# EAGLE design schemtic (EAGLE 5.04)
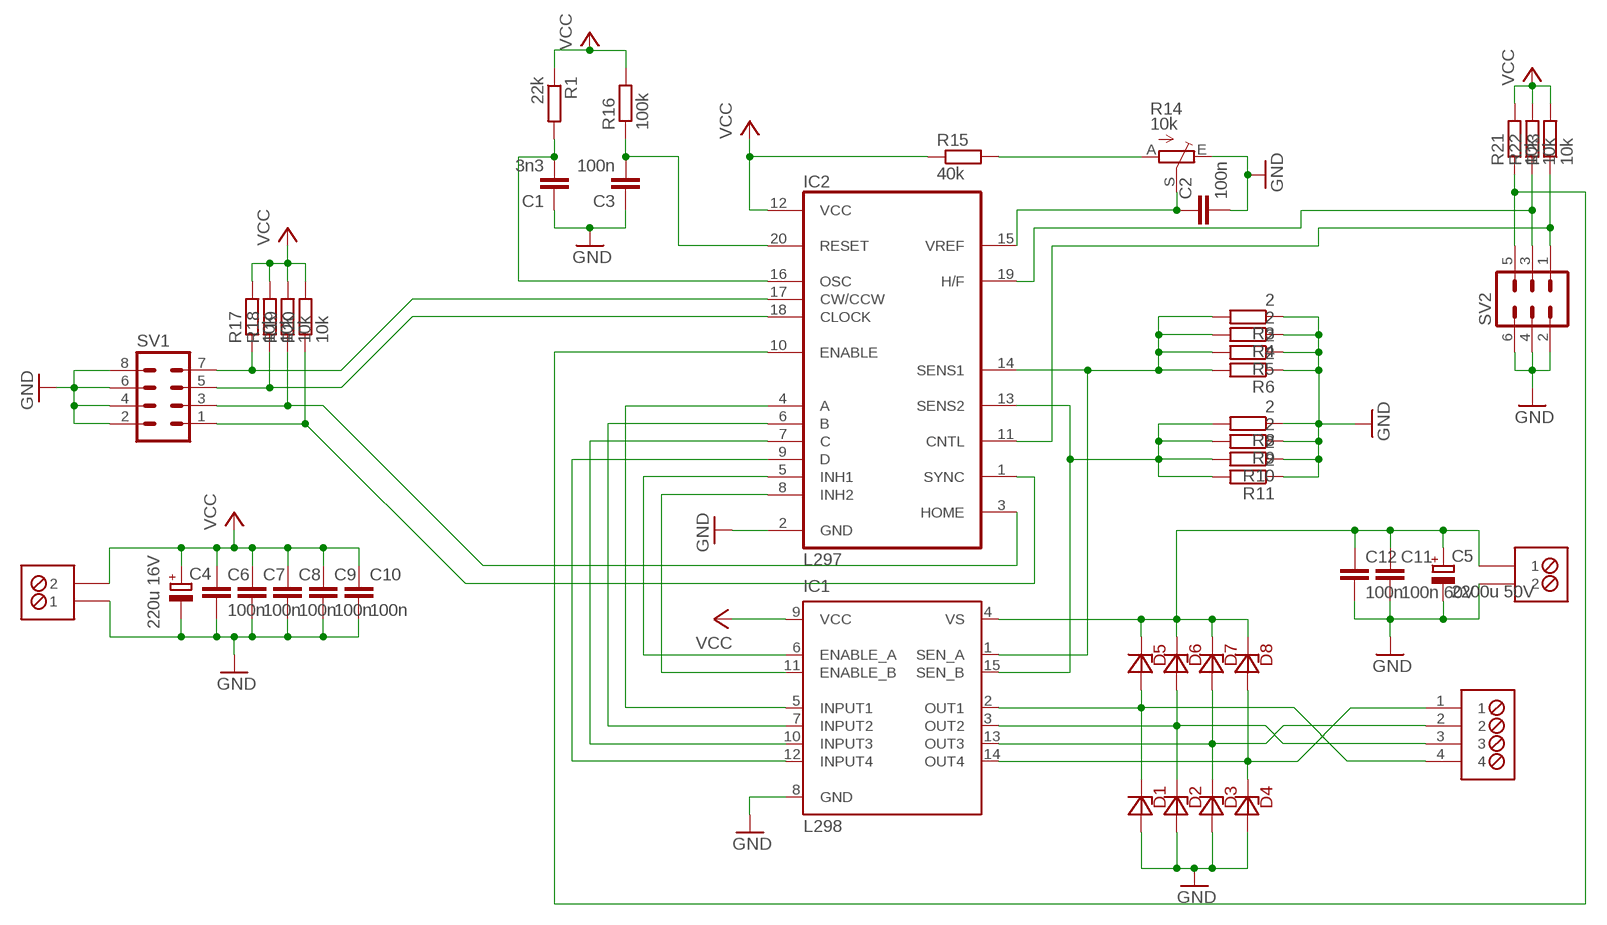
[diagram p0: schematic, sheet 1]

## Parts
C1  3n3  C-EU050-030X075  [C050-030X075]
C2  100n  C-EUC0603  [C0603]
C3  100n  C-EUC0805  [C0805]
C4  220u 16V  CPOL-EUE5-13  [E5-13]
C5  2200u 50V  CPOL-EUE7.5-16  [E7,5-16]
C6  100n  C-EUC0603  [C0603]
C7  100n  C-EUC0603  [C0603]
C8  100n  C-EUC0603  [C0603]
C9  100n  C-EUC0603  [C0603]
C10  100n  C-EUC0603  [C0603]
C11  100n 60V  C-EU050-055X075  [C050-055X075]
C12  100n  C-EU050-055X075  [C050-055X075]
CON1  LISTAWA_ZACISKOWA5MM_4X1  [LISTAWA_ZACISKOWA5MM_4X1]
CON2  LISTWA_ZACISKOWA5MM_2X1  [LISTWA_ZACISKOWA5MM_2X1]
CON3  LISTWA_ZACISKOWA5MM_2X1  [LISTWA_ZACISKOWA5MM_2X1]
D1  1N5822  [DO-27]
D2  1N5822  [DO-27]
D3  1N5822  [DO-27]
D4  1N5822  [DO-27]
D5  1N5822  [DO-27]
D6  1N5822  [DO-27]
D7  1N5822  [DO-27]
D8  1N5822  [DO-27]
IC1  L298  [MULTIWATT-15]
IC2  L297  [DIL20]
R1  22k  R-EU_0207/7  [0207/7]
R3  2  R-EU_0411/15  [0411/15]
R4  2  R-EU_0411/15  [0411/15]
R5  2  R-EU_0411/15  [0411/15]
R6  2  R-EU_0411/15  [0411/15]
R8  2  R-EU_0411/15  [0411/15]
R9  2  R-EU_0411/15  [0411/15]
R10  2  R-EU_0411/15  [0411/15]
R11  2  R-EU_0411/15  [0411/15]
R14  10k  TRIM_EU-S63X  [S63X]
R15  40k  R-EU_0207/7  [0207/7]
R16  100k  R-EU_0207/7  [0207/7]
R17  10k  R-EU_R0603  [R0603]
R18  10k  R-EU_R0603  [R0603]
R19  10k  R-EU_R0603  [R0603]
R20  10k  R-EU_R0603  [R0603]
R21  10k  R-EU_R0603  [R0603]
R22  10k  R-EU_R0603  [R0603]
R23  10k  R-EU_R0603  [R0603]
SV1  MA04-2  [MA04-2]
SV2  MA03-2  [MA03-2]

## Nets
GND: C1.1 C2.2 C3.1 C4.- C5.- C6.2 C7.2 C8.2 C9.2 C10.2 C11.2 C12.2 CON2.P$2 CON3.P$1 D1.CAT D2.CAT D3.CAT D4.CAT IC1.8(GND) IC2.2(GND) R3.1 R4.1 R5.1 R6.1 R8.1 R9.1 R10.1 R11.1 R14.E SV1.2 SV1.4 SV1.6 SV1.8 SV2.2 SV2.4 SV2.6
N$1: IC1.5(INPUT1) IC2.4(A)
N$2: IC1.7(INPUT2) IC2.6(B)
N$3: IC1.10(INPUT3) IC2.7(C)
N$4: IC1.12(INPUT4) IC2.9(D)
N$5: IC1.6(ENABLE_A) IC2.5(INH1)
N$6: IC1.11(ENABLE_B) IC2.8(INH2)
N$7: IC1.1(SEN_A) IC2.14(SENS1) R3.2 R4.2 R5.2 R6.2
N$8: IC1.15(SEN_B) IC2.13(SENS2) R8.2 R9.2 R10.2 R11.2
N$9: C1.2 IC2.16(OSC) R1.2
N$10: CON1.4 D1.AN D5.CAT IC1.2(OUT1)
N$11: IC2.18(CLOCK) R18.1 SV1.5
N$12: IC2.17(CW/CCW) R17.1 SV1.7
N$13: CON1.1 D4.AN D8.CAT IC1.14(OUT4)
N$14: C2.1 IC2.15(VREF) R14.S
N$15: C5.+ C11.1 C12.1 CON2.P$1 D5.AN D6.AN D7.AN D8.AN IC1.4(VS)
N$16: R14.A R15.2
N$17: IC2.19(H/F) R22.1 SV2.3
N$18: IC2.11(CNTL) R23.1 SV2.1
N$19: C3.2 IC2.20(RESET) R16.1
N$20: CON1.2 D3.AN D7.CAT IC1.13(OUT3)
N$22: IC2.10(ENABLE) R21.1 SV2.5
N$25: IC2.3(HOME) R19.1 SV1.3
N$26: IC2.1(SYNC) R20.1 SV1.1
N$27: CON1.3 D2.AN D6.CAT IC1.3(OUT2)
VCC: C4.+ C6.1 C7.1 C8.1 C9.1 C10.1 CON3.P$2 IC1.9(VCC) IC2.12(VCC) R1.1 R15.1 R16.2 R17.2 R18.2 R19.2 R20.2 R21.2 R22.2 R23.2

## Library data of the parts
C1-C3 C6-C12 = rcl:C-EU: CAPACITOR, European symbol
C4 C5 = rcl:CPOL-EU: POLARIZED CAPACITOR, European symbol
CON1 = konektory:LISTAWA_ZACISKOWA5MM_4X1
CON2 CON3 = konektory:LISTWA_ZACISKOWA5MM_2X1
D1-D8 = diody:1N5822: SCHOTTKY RECTIFIER 3A 40V
IC1 = st-microelectronics:L298: DUAL FULL-BRIDGE DRIVER
IC2 = st-microelectronics:L297: STEPPER MOTOR CONTROLLER
R1 R3-R6 R8-R11 R15-R23 = rcl:R-EU_: RESISTOR, European symbol
R14 = pot:TRIM_EU-: POTENTIOMETER
SV1 = con-lstb:MA04-2: PIN HEADER
SV2 = con-lstb:MA03-2: PIN HEADER

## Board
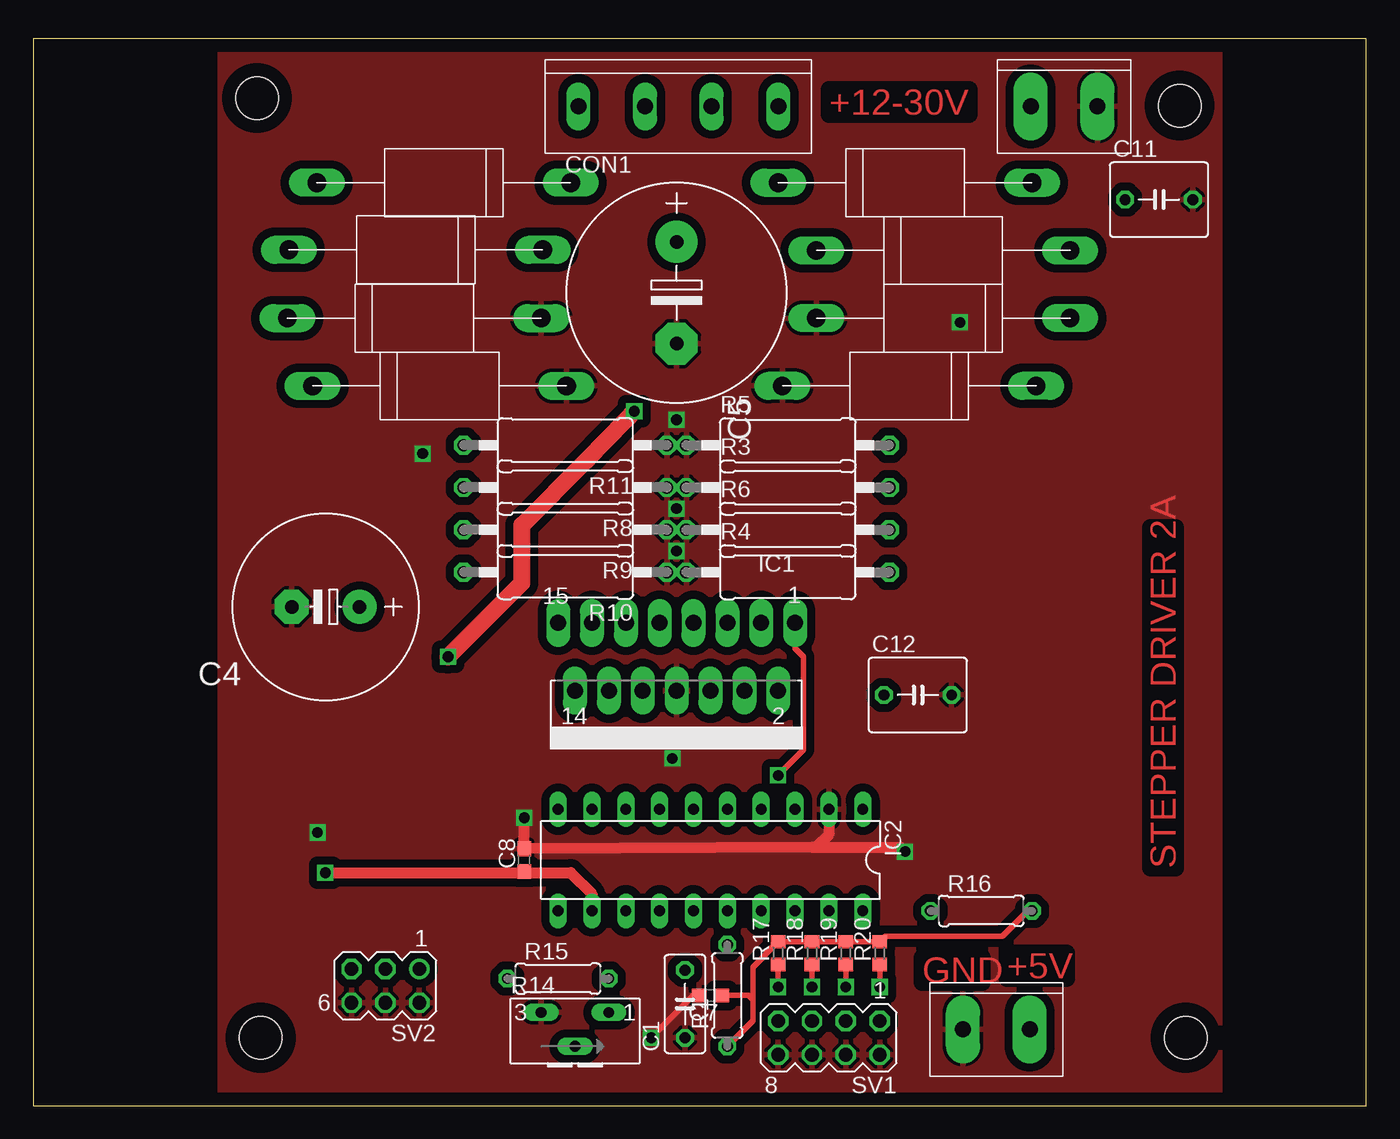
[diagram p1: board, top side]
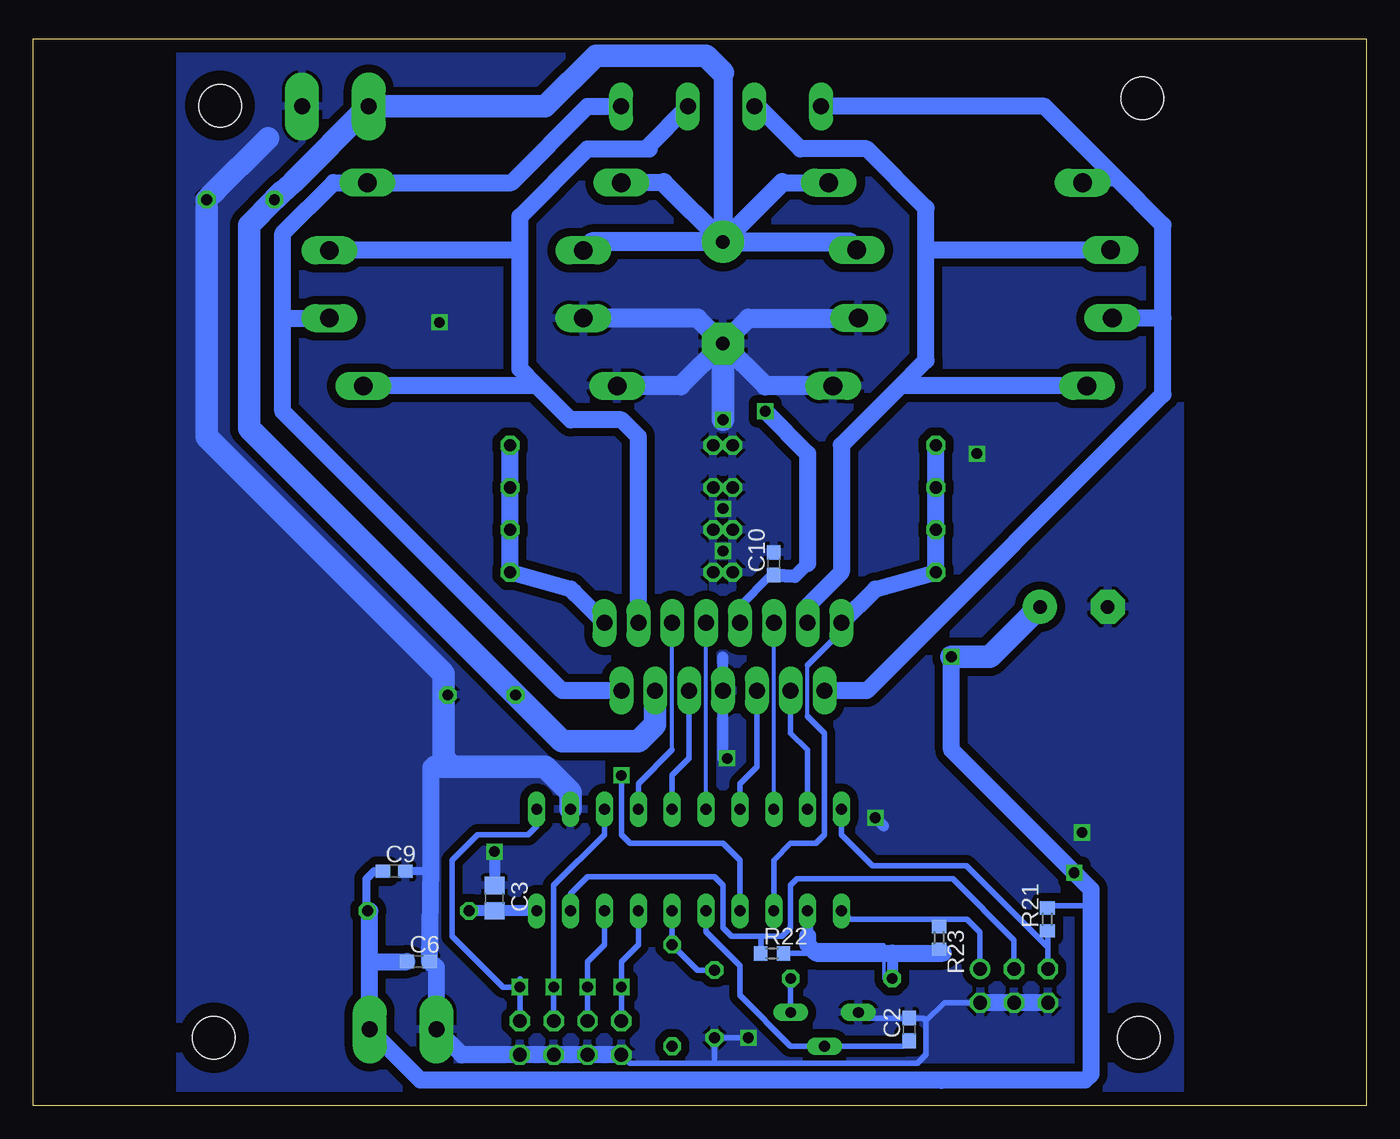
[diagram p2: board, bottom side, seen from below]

Size 100 x 80 mm. Coordinates in mm from the lower left corner, seen from the top.
Outline: 0,0 100,0 100,80 0,80 0,0
Copper layers (1*16): Top 0.035mm / dielectric 1.5mm / Bottom 0.035mm
Design rules "default": minimum track width 10mil, minimum drill 24mil, track to track 8mil, track to pad 8mil, pad to pad 8mil, via to via 8mil, smd to smd 8mil, copper to edge 40mil, drill to drill 8mil, minimum pad ring 10mil, minimum via ring 8mil, stop-mask expansion 4mil, vias tented up to drill 0mil, thermal gap 10mil
Holes 3.2 mm at 17.05,5.08 86.45,5.08 16.78,75.56 86,75

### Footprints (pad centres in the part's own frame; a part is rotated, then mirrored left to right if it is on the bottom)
C050-030X075 = drill 0.813 octagon: 1 -2.54,0; 2 2.54,0
C0603 = smd 1.1 x 1: 1 -0.85,0; 2 0.85,0
C0805 = smd 1.3 x 1.5: 1 -0.95,0; 2 0.95,0
E5-13 = drill 1.016 pad 2.54 round: + -2.54,0 | drill 1.016 pad 2.54 octagon: - 2.54,0
E7,5-16 = drill 1.016 pad 3.15 round: + -3.81,0 | drill 1.016 pad 3.15 octagon: - 3.81,0
C050-055X075 = drill 0.813 octagon: 1 -2.54,0; 2 2.54,0
LISTAWA_ZACISKOWA5MM_4X1 = drill 1.2 long: 1 -8,0; 2 -3,0; 3 2,0; 4 7,0
LISTWA_ZACISKOWA5MM_2X1 = drill 1.2 pad 2.54 long: P$1 -2,0; P$2 3,0
DO-27 = drill 1.4 long: AN -8.89,0; CAT 10.16,0
MULTIWATT-15 = drill 1.2 long: 1 -8.89,-7.62; 2 -7.62,-2.54; 3 -6.35,-7.62; 4 -5.08,-2.54; 5 -3.81,-7.62; 6 -2.54,-2.54; 7 -1.27,-7.62; 8 0,-2.54; 9 1.27,-7.62; 10 2.54,-2.54; 11 3.81,-7.62; 12 5.08,-2.54; 13 6.35,-7.62; 14 7.62,-2.54; 15 8.89,-7.62
DIL20 = drill 0.813 long: 1 -11.43,-3.81; 2 -8.89,-3.81; 3 -6.35,-3.81; 4 -3.81,-3.81; 5 -1.27,-3.81; 6 1.27,-3.81; 7 3.81,-3.81; 8 6.35,-3.81; 9 8.89,-3.81; 10 11.43,-3.81; 11 11.43,3.81; 12 8.89,3.81; 13 6.35,3.81; 14 3.81,3.81; 15 1.27,3.81; 16 -1.27,3.81; 17 -3.81,3.81; 18 -6.35,3.81; 19 -8.89,3.81; 20 -11.43,3.81
0207/7 = drill 0.813 octagon: 1 -3.81,0; 2 3.81,0
0411/15 = drill 0.914 octagon: 1 -7.62,0; 2 7.62,0
S63X = drill 0.813 long: A 2.54,0; E -2.54,0; S 0,-2.54
R0603 = smd 1 x 1.1: 1 -0.85,0; 2 0.85,0
MA04-2 = drill 1.016 octagon: 1 -3.81,-1.27; 2 -3.81,1.27; 3 -1.27,-1.27; 4 -1.27,1.27; 5 1.27,-1.27; 6 1.27,1.27; 7 3.81,-1.27; 8 3.81,1.27
MA03-2 = drill 1.016 round: 1 -2.54,-1.27 | drill 1.016 octagon: 2 -2.54,1.27; 3 0,-1.27; 4 0,1.27; 5 2.54,-1.27; 6 2.54,1.27

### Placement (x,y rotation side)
C1  48.9,7.62 90 top
C2  34.29,5.71 90 bottom
C3  65.41,15.56 270 bottom
C4  21.93,37.4 180 top
C5  48.26,60.96 270 top
C6  71.12,10.79 0 bottom
C7  50.8,8.26 180 top
C8  36.83,18.41 90 top
C9  72.93,17.57 0 bottom
C10  44.45,40.64 90 bottom
C11  84.45,67.94 0 top
C12  66.36,30.8 0 top
CON1  48.9,74.93 0 top
CON2  76.83,74.93 0 top
CON3  71.75,5.71 0 top
D1  68.9,59.05 180 top
D2  66.36,53.98 180 top
D3  29.84,53.98 0 top
D4  27.94,59.05 0 top
D5  64.77,69.22 0 top
D6  67.63,64.14 0 top
D7  29.33,64.18 180 top
D8  31.43,69.22 180 top
IC1  48.26,28.57 180 top
IC2  50.8,18.41 180 top
R1  52.07,8.26 90 top
R3  56.61,46.35 0 top
R4  56.61,40.01 0 top
R5  56.61,49.53 0 top
R6  56.61,43.18 0 top
R8  39.91,46.35 180 top
R9  39.91,43.18 180 top
R10  39.91,40.01 180 top
R11  39.91,49.53 180 top
R14  40.64,6.99 0 top
R15  39.37,9.53 0 top
R16  71.12,14.61 0 top
R17  55.88,11.43 90 top
R18  58.42,11.43 90 top
R19  60.96,11.43 90 top
R20  63.5,11.43 90 top
R21  23.92,13.96 90 bottom
R22  44.58,11.41 0 bottom
R23  32.05,12.57 270 bottom
SV1  59.69,5.08 180 top
SV2  26.41,8.98 180 top

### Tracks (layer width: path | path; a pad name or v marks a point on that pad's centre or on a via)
GND  (via drill 0.8, 0.8 pad 0.81)
  Top 0.406: C7.2 49.53,8.26 v46.35,5.08
  Top 0.813: v36.83,21.59 C8.2 58.42,19.36 | IC2.2 59.69,20.32 58.73,19.36 58.42,19.36 | v65.41,19.05 65.09,19.36 58.42,19.36
  Bottom 0.406: R14.E 37.68,6.57 C2.2 33.23,6.57 33.02,6.35 | 33.02,6.35 33.02,3.81 33.66,3.17 48.9,3.17 | 33.02,6.35 31.66,7.71 SV2.4 | v46.35,5.08 C1.1 48.9,3.17 | 48.9,3.17 55.24,3.17 SV1.8 | C12.2 68.9,32.07 69.37,32.54
  Bottom 0.61: C9.2 70.59,17.57 70.17,18
  Bottom 0.813: 48.26,33.66 IC1.8 48.26,26.04 v47.94,26.04 | v36.83,21.59 36.2,20.95 | v65.41,19.05 C3.1
  Bottom 1.27: SV1.8 SV1.6 | SV1.6 SV1.4 | SV1.4 SV1.2 67.85,3.81 CON3.P$1 69.75,10.38 C6.2 70.17,18 70.17,25.4 69.85,25.4 | SV1.6 SV1.4 | SV2.6 SV2.4 SV2.2
  Bottom 1.422: D4.CAT 46.35,59.05 C5.- | D1.CAT 50.16,59.05 C5.- | D3.CAT 45.09,53.98 C5.- | D2.CAT 51.44,53.98 C5.-
  Bottom 1.676: C5.- v48.26,51.44 | IC2.2 59.69,23.5 61.59,25.4 68.58,25.4 | 69.85,25.4 68.58,25.4 | 86.68,68.26 82.38,72.56 | 68.58,25.4 69.22,26.04 69.22,32.38 69.37,32.54 87,50.16 C11.2 86.68,68.26 | 86.68,68.26 86.36,68.58
  other vias: 48.26,44.77 48.26,41.59 21.32,20.48 29.21,48.9 69.53,58.74
  pour Bottom (isolate 0.61): 24,1 89,1 89,80 14,80 14,4 14,1
  pour Top (isolate 0.61): 14,1 14,80 89,80 89,1
N$1
  Bottom 0.305: 52.07,26.67 IC1.5
  Bottom 0.406: IC2.4 54.61,24.13 52.07,26.67
N$2
  Bottom 0.305: IC2.6 IC1.7
N$3
  Bottom 0.406: IC2.7 46.99,24.13 45.72,25.4 IC1.10
N$4
  Bottom 0.406: IC2.9 41.91,26.67 43.18,27.94 IC1.12
N$5
  Bottom 0.406: IC2.5 52.07,24.77 50.8,26.04 IC1.6
N$6
  Bottom 0.305: IC2.8 IC1.11
N$7  (via drill 0.8)
  Top 0.406: v55.88,24.77 57.78,26.67 57.78,33.66 57.15,34.29 IC1.1
  Bottom 0.406: IC2.14 46.99,18.41 48.26,19.68 55.24,19.68 55.88,20.32 v55.88,24.77 | 59.37,38.42 60.01,38.42
  Bottom 1.27: IC1.1 59.37,38.42 59.69,38.73 R4.2 R6.2 R3.2 R5.2
N$8
  Bottom 0.305: 41.91,29.21 41.91,33.02
  Bottom 0.406: IC2.13 44.45,18.41 43.18,19.68 41.27,19.68 40.64,20.32 40.64,27.94 41.91,29.21 | 41.91,33.02 39.37,35.56 IC1.15
  Bottom 1.27: IC1.15 36.83,38.73 R10.2 R9.2 R8.2 R11.2
N$9
  Bottom 0.406: IC2.16 R1.2 50.16,10.16 C1.2
N$10
  Bottom 1.27: 81.28,59.05 81.28,65.41 77.47,69.22 D5.CAT 64.14,69.22 58.42,74.93 CON1.4 | 81.28,59.05 D1.AN | IC1.2 60.33,31.11 81.28,52.07 81.28,59.05
N$11  (via drill 0.8)
  Top 0.406: v58.42,8.89 R18.1
  Bottom 0.406: SV1.5 v58.42,8.89 58.42,10.79 57.15,12.06 IC2.18
N$12  (via drill 0.8)
  Top 0.406: v55.88,8.89 R17.1
  Bottom 0.406: SV1.7 v55.88,8.89 55.88,10.79 54.61,12.06 IC2.17
N$13
  Bottom 1.27: 15.24,59.05 15.24,66.04 18.73,69.53 | 18.73,69.53 24.13,74.93 CON1.1 | 18.73,69.53 21.59,69.53 | 15.24,59.05 D4.AN | IC1.14 37.47,31.11 15.24,53.34 15.24,59.05 | 21.59,69.53 22.54,69.53 | 21.59,69.53 D8.CAT
N$14
  Bottom 0.406: C2.1 34.71,4.45 R14.S 43.18,4.45 46.99,8.26 46.99,10.48 49.53,13.02 IC2.15
N$15
  Bottom 1.27: 43.81,69.22 D8.AN | 58.1,64.77 D6.AN | 38.73,64.77 38.73,64.7 D7.AN | 52.7,69.22 D5.AN
  Bottom 1.422: C5.+ 38.73,64.77 | C5.+ 58.1,64.77 | C5.+ 43.81,69.22 | C5.+ 52.7,69.22 | 48.26,77.47 C5.+
  Bottom 1.676: IC1.4 53.34,28.57 54.61,27.3 60.33,27.3 | 60.33,27.3 C12.1 | 60.33,27.3 83.82,50.8 83.82,66.04 C11.1 | C11.1 81.28,68.58 | 48.26,77.47 49.53,78.74 57.78,78.74 61.59,74.93 CON2.P$1 80.55,69.22 C11.1
N$16
  Bottom 0.406: R14.A R15.2
N$17
  Bottom 0.406: IC2.19 59.69,15.88 58.42,17.14 48.9,17.14 48.26,16.51 48.26,13.34 47.62,12.7 45.4,12.7 | 45.4,12.7 43.81,12.7 43.18,13.34 43.18,16.51 42.69,17 31,17 26.41,12.41 SV2.3 | R22.1 45.42,12.68 45.4,12.7
N$18
  Bottom 0.406: IC2.11 38.73,13.97 32,13.97 | 32,13.97 29.97,13.97 29,13 29,10.29 SV2.1 | R23.1 32.05,13.93 32,13.97
N$19
  Bottom 0.813: R16.1 C3.2 IC2.20
N$20
  Bottom 1.27: 35.24,53.66 33.02,55.88 33.02,64 | 33.02,64 33.02,67.31 37.47,71.75 42.45,71.75 45.62,74.93 CON1.2 | D3.AN 34.92,53.98 35.24,53.66 | IC1.13 41.91,37.47 39.37,40.01 39.37,49.53 35.24,53.66 | D7.CAT 33.02,64.18 33.02,64
N$22
  Bottom 0.406: IC2.10 39.37,20.32 37.05,18 30,18 23.88,11.88 23.88,13.07 | SV2.5 23.88,13.07 | 23.88,13.07 R21.1
N$25  (via drill 0.8)
  Top 0.406: v60.96,8.89 R19.1
  Bottom 0.406: SV1.3 v60.96,8.89 60.96,16.51 57.15,20.32 IC2.3
N$26  (via drill 0.8)
  Top 0.406: v63.5,8.89 R20.1
  Bottom 0.406: SV1.1 v63.5,8.89 | v63.5,8.89 63.5,9.53 | IC2.1 62.23,20.95 62.87,20.32 66.67,20.32 68.58,18.41 68.58,12.7 64.77,8.89 v63.5,8.89
N$27
  Bottom 1.27: IC1.3 54.61,50.16 55.88,51.44 59.69,51.44 62.23,53.98 | 62.23,53.98 63.5,55.24 63.5,64.14 | 53.98,71.75 58.42,71.75 63.5,66.67 63.5,65 63.5,64.14 | 53.98,71.75 53.8,71.75 | 62.23,53.98 D2.AN | CON1.3 53.98,71.85 53.98,71.75 | 63.5,64.14 D6.CAT
VCC  (via drill 0.8, 0.8 pad 0.81)
  Top 0.406: 53.98,7.94 53.98,10.38 R17.2 R18.2 R19.2 R20.2 63.92,12.7 72.71,12.7 74.61,14.61 R16.2 | 53.98,7.94 53.98,6.35 R1.1 | C7.1 53.66,8.26 53.98,7.94 | 36.51,17.46 36.83,17.46
  Top 0.813: C8.1 36.83,17.46 40.32,17.46 41.91,15.88 IC2.12 | v21.91,17.46 36.51,17.46 36.83,17.46
  Top 1.27: v31.11,33.66 36.66,39.2 36.66,43.53 41.56,48.44 44.45,51.44 v45.09,52.07
  Bottom 0.254: R15.1 36.2,9.53 36.2,12.06 41.27,12.06 41.59,11.75
  Bottom 0.406: R23.2 32.05,11.47 32,11.43 | R22.2 40.34,11.41 40.32,11.43 | R21.2 23.74,15 20.64,15
  Bottom 0.61: C10.1 44.77,39.69 46.99,37.47 IC1.9 | C9.1 74.42,17.57 75,17 75,14.68 R16.2
  Bottom 0.813: IC2.12 41.91,12.7 | 35.56,11.43 R15.1
  Bottom 1.016: C10.1 42.86,39.69 41.91,40.64
  Bottom 1.27: 74.75,10.79 CON3.P$2 70.94,1.91 32,1.91 | 74.75,10.79 74.75,14.61 R16.2 | 74.75,10.79 C6.1 | 31.75,11.43 32,11.43 35.56,11.43 40.32,11.43 41.27,11.43 41.59,11.75 41.91,12.06 41.91,12.7 | v31.11,33.66 31.11,26.67 v21.91,17.46 20.64,16.19 20.64,15 20.64,2.36 21.09,1.91 32,1.91 | 41.91,40.64 41.91,48.9 v45.09,52.07 | 32,1.91 31.75,1.91
  Bottom 1.676: v31.11,33.66 28.21,33.66 C4.+

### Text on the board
Top: +12-30V | STEPPER DRIVER 2A | +5V | GND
